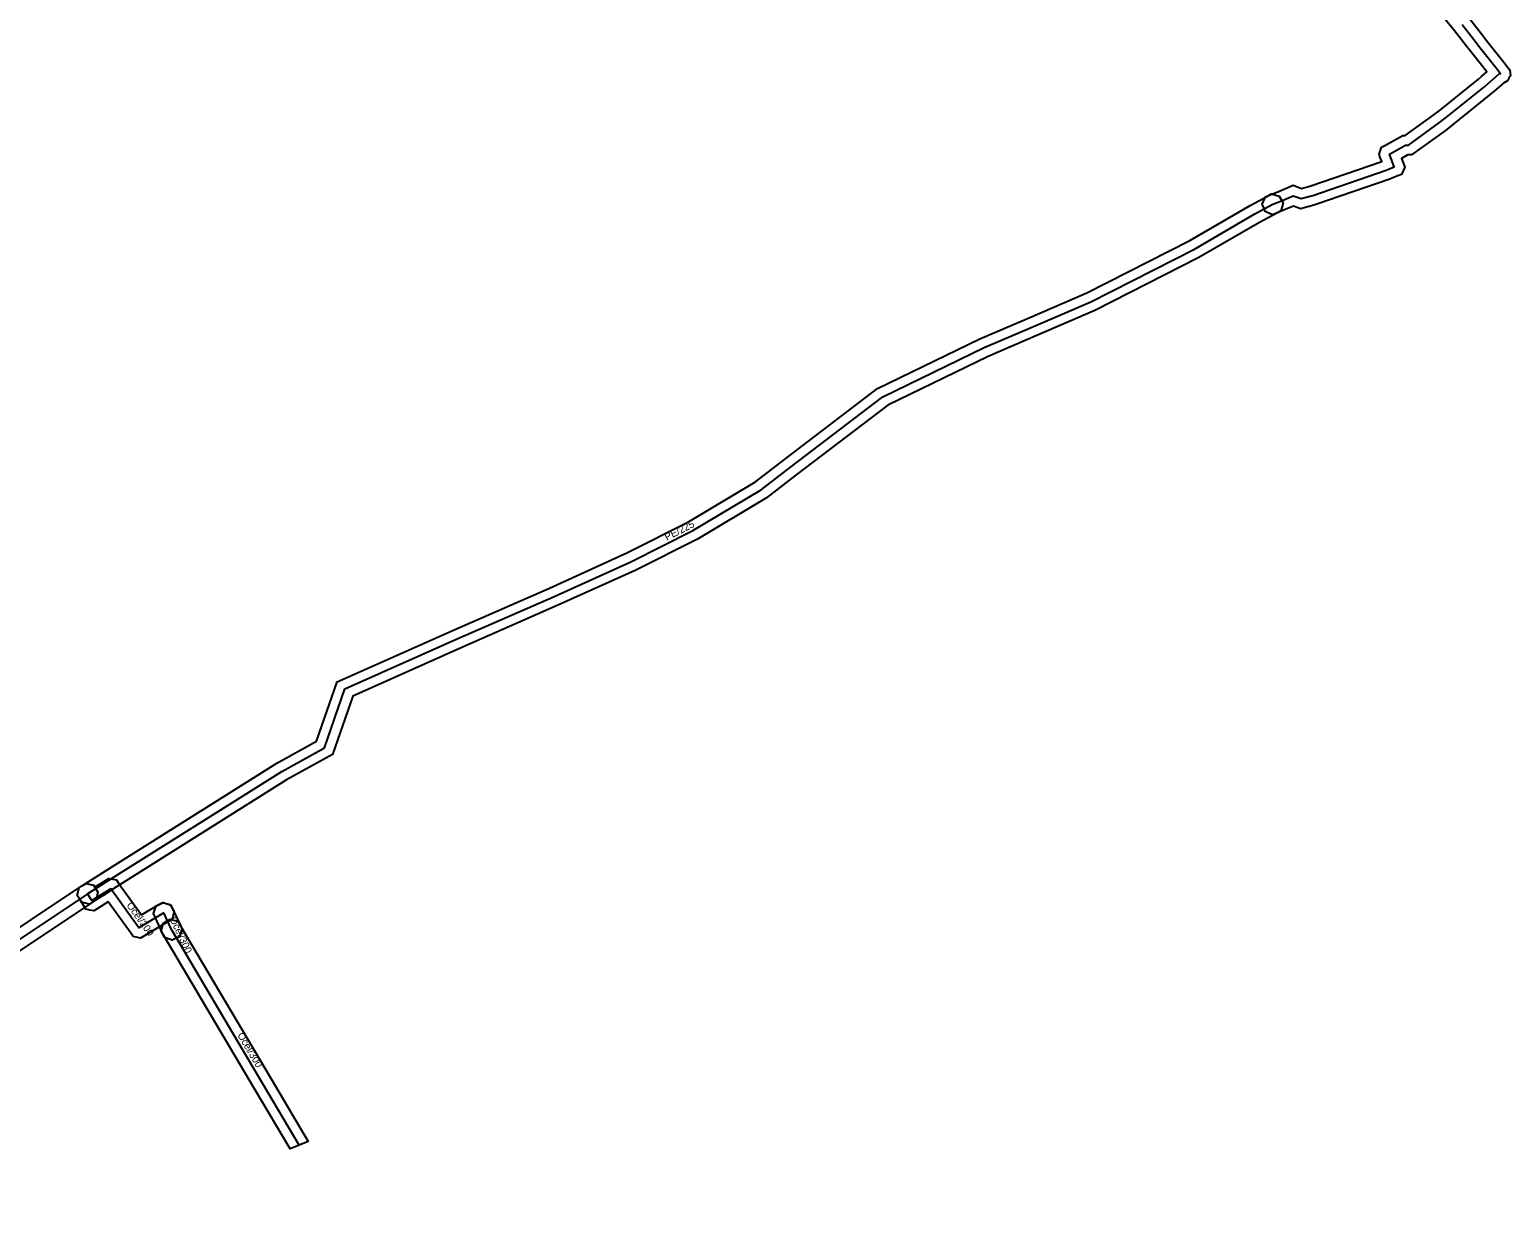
# Model space of a CAD drawing. Extents: x -760566 to -760255, y -976320 to -976047.
# Drawn here: x -760408.2 to -760255.3, y -976295.8 to -976174.5 of the extents above; entities that cross this region are included whole.
import ezdxf

# ---------------------------------------------------------------- set-up
doc = ezdxf.new("R2010")
doc.units = 0
for name, color, linetype in [('1', 7, 'Continuous'), ('24', 7, 'Continuous'), ('30', 7, 'Continuous')]:
    doc.layers.add(name, color=color, linetype=linetype)

msp = doc.modelspace()

# ---------------------------------------------------------------- linework, layer by layer
at = {"layer": '1'}
for points in [[(-760259.47, -976173.4), (-760258.25, -976174.97), (-760257.59, -976175.82), (-760255.82, -976178.07), (-760255.52, -976178.44), (-760255.32, -976178.67), (-760255.27, -976179.28), (-760255.41, -976179.55), (-760255.56, -976179.82), (-760255.98, -976180.04), (-760256.95, -976180.87), (-760257.28, -976181.16), (-760261.24, -976184.34), (-760261.96, -976184.93), (-760265.48, -976187.46), (-760265.84, -976187.46), (-760266.52, -976187.83), (-760266.32, -976188.35), (-760266.18, -976188.73), (-760266.51, -976189.47), (-760266.89, -976189.63), (-760267.56, -976189.9), (-760267.73, -976189.97), (-760275.36, -976192.59), (-760275.82, -976192.72), (-760276.93, -976193.03), (-760277.66, -976192.76), (-760278.52, -976193.11), (-760279.43, -976193.49), (-760279.82, -976193.64), (-760280.58, -976193.32), (-760280.74, -976192.94), (-760280.89, -976192.55), (-760280.57, -976191.79), (-760280.19, -976191.63), (-760279.28, -976191.27), (-760277.7, -976190.6), (-760276.83, -976190.93), (-760276.36, -976190.8), (-760275.96, -976190.69), (-760268.54, -976188.13), (-760268.7, -976187.72), (-760268.83, -976187.37), (-760268.57, -976186.67), (-760268.24, -976186.49), (-760266.36, -976185.46), (-760266.12, -976185.46), (-760263.18, -976183.33), (-760262.49, -976182.79), (-760258.56, -976179.62), (-760258.25, -976179.36), (-760257.71, -976178.89), (-760259.16, -976177.06), (-760259.83, -976176.21), (-760261.03, -976174.64), (-760269.58, -976164.14)], [(-760412.99, -976269.77), (-760402.99, -976263.12), (-760402.77, -976262.96), (-760402.69, -976262.92), (-760402.34, -976262.71), (-760401.54, -976262.91), (-760401.32, -976263.27), (-760401.11, -976263.62), (-760401.31, -976264.42), (-760401.67, -976264.64), (-760401.7, -976264.66), (-760401.89, -976264.78), (-760411.87, -976271.43)]]:
    msp.add_lwpolyline(points, dxfattribs=at)
for points in [[(-760403.07, -976263.16), (-760402.72, -976262.94), (-760401.67, -976262.27), (-760400.25, -976261.37), (-760382.65, -976250.29), (-760378.53, -976248.02), (-760376.41, -976241.89), (-760364.34, -976236.51), (-760354.5, -976232.2), (-760346.51, -976228.58), (-760340.15, -976225.38), (-760333.2, -976221.22), (-760330.22, -976218.94), (-760320.61, -976211.58), (-760310.04, -976206.45), (-760304.9, -976204.25), (-760299.01, -976201.72), (-760288.38, -976196.31), (-760282.15, -976192.69), (-760280.29, -976191.68), (-760279.92, -976191.48), (-760279.13, -976191.72), (-760278.93, -976192.08), (-760278.73, -976192.45), (-760278.97, -976193.24), (-760279.33, -976193.44), (-760281.17, -976194.43), (-760287.42, -976198.07), (-760298.17, -976203.54), (-760304.11, -976206.09), (-760309.2, -976208.27), (-760319.55, -976213.3), (-760329, -976220.52), (-760332.08, -976222.88), (-760339.19, -976227.14), (-760345.65, -976230.38), (-760353.68, -976234.02), (-760363.54, -976238.33), (-760374.81, -976243.37), (-760376.89, -976249.4), (-760381.63, -976252.01), (-760399.19, -976263.07), (-760400.59, -976263.95), (-760401.64, -976264.62), (-760401.99, -976264.85), (-760402.8, -976264.67), (-760403.02, -976264.32), (-760403.25, -976263.97)], [(-760401.56, -976262.9), (-760401.42, -976263.11), (-760400.33, -976262.42), (-760399.99, -976262.2), (-760399.21, -976262.35), (-760398.98, -976262.68), (-760396.61, -976265.97), (-760394.82, -976264.91), (-760394.46, -976264.7), (-760393.66, -976264.9), (-760393.45, -976265.26), (-760393.24, -976265.62), (-760393.44, -976266.42), (-760393.8, -976266.63), (-760396.38, -976268.16), (-760396.71, -976268.36), (-760397.47, -976268.2), (-760397.7, -976267.88), (-760400.05, -976264.61), (-760401.2, -976265.33), (-760401.54, -976265.56), (-760401.95, -976265.47), (-760402.35, -976265.38), (-760402.58, -976265.03), (-760403.03, -976264.32), (-760403.25, -976263.96), (-760403.07, -976263.16), (-760402.71, -976262.94), (-760402.36, -976262.71)], [(-760394.24, -976268.29), (-760394.42, -976267.91), (-760395.22, -976266.19), (-760395.39, -976265.82), (-760395.11, -976265.04), (-760394.73, -976264.86), (-760394.36, -976264.69), (-760393.58, -976264.97), (-760393.4, -976265.35), (-760392.6, -976267.07), (-760392.43, -976267.44), (-760392.71, -976268.22), (-760393.09, -976268.4), (-760393.46, -976268.57)], [(-760383.23, -976282.91), (-760379.4, -976289.36), (-760381.26, -976290.15), (-760384.95, -976283.93), (-760394.37, -976268), (-760394.58, -976267.64), (-760394.38, -976266.84), (-760394.02, -976266.63), (-760393.66, -976266.42), (-760392.86, -976266.62), (-760392.65, -976266.98)]]:
    msp.add_lwpolyline(points, close=True, dxfattribs=at)
at = {"layer": '24'}
for points in [[(-760279.81, -976192.56), (-760278.9, -976192.19), (-760277.68, -976191.68), (-760276.88, -976191.98), (-760276.09, -976191.76), (-760275.66, -976191.64), (-760268.08, -976189.03), (-760267.93, -976188.97), (-760267.26, -976188.7), (-760267.76, -976187.37), (-760266.1, -976186.46), (-760265.8, -976186.46), (-760262.57, -976184.13), (-760261.87, -976183.56), (-760257.92, -976180.39), (-760257.6, -976180.11), (-760256.38, -976179.06), (-760256.29, -976179.07), (-760256.6, -976178.69), (-760258.37, -976176.44), (-760259.04, -976175.59), (-760260.25, -976174.02)], [(-760402.18, -976263.78), (-760401.13, -976263.11), (-760399.72, -976262.22), (-760382.14, -976251.15), (-760377.71, -976248.71), (-760375.61, -976242.63), (-760363.94, -976237.42), (-760354.09, -976233.11), (-760346.08, -976229.48), (-760339.67, -976226.26), (-760332.64, -976222.05), (-760329.61, -976219.73), (-760320.08, -976212.44), (-760309.62, -976207.36), (-760304.51, -976205.17), (-760298.59, -976202.63), (-760287.9, -976197.19), (-760281.66, -976193.56), (-760279.81, -976192.56)], [(-760402.18, -976263.78), (-760402.23, -976263.81), (-760402.44, -976263.95), (-760412.43, -976270.6), (-760417.08, -976273.85), (-760418.69, -976275.04), (-760426.33, -976280.32), (-760426.84, -976280.67), (-760436.91, -976287.51), (-760446.44, -976294.77), (-760447.73, -976295.77)], [(-760394.31, -976265.77), (-760396.89, -976267.3), (-760399.79, -976263.26), (-760401.73, -976264.49), (-760402.18, -976263.78)], [(-760393.51, -976267.49), (-760394.31, -976265.77)], [(-760380.33, -976289.75), (-760384.09, -976283.42), (-760393.51, -976267.49)]]:
    msp.add_lwpolyline(points, dxfattribs=at)

# ---------------------------------------------------------------- texts
at = {"layer": '30'}
for s, rotation, p in [('PE/225', 26.6722, (-760342.38, -976227.32)), ('Ocel/200', 305.6716, (-760398.21, -976264.98)), ('Ocel/300', 294.9439, (-760393.73, -976266.38)), ('Ocel/300', 300.5974, (-760386.75, -976278.38))]:
    msp.add_text(s, height=0.75, rotation=rotation, dxfattribs=at).set_placement(p)

doc.saveas('drawing.dxf')
